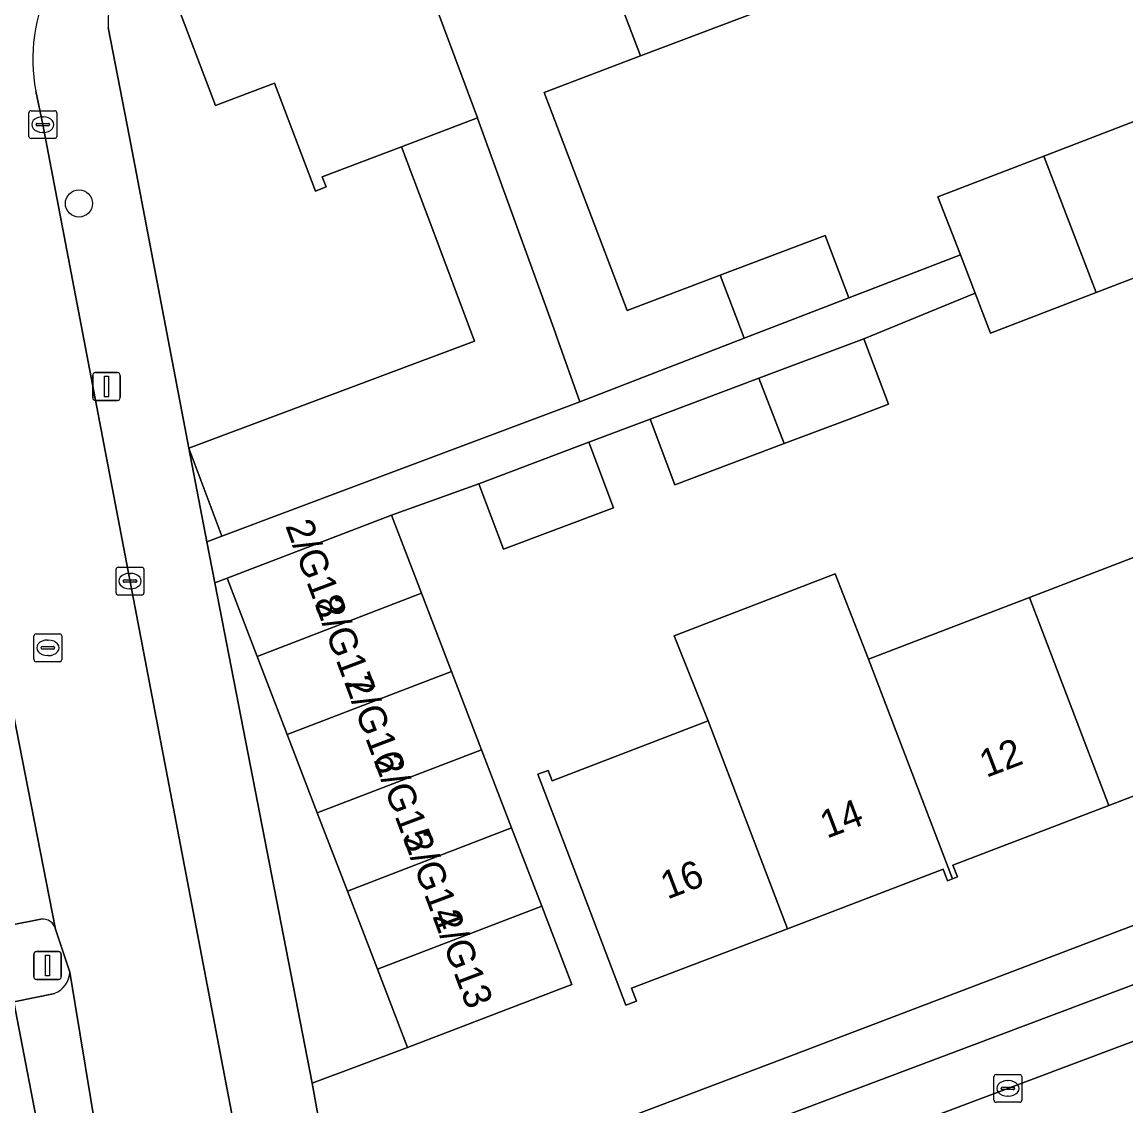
# Model space of a CAD drawing. Extents: x 159262 to 160143, y 383399 to 384319.
# Drawn here: x 159355.19 to 159394.93, y 383839.14 to 383878.17 of the extents above; entities that cross this region are included whole.
import ezdxf

# ---------------------------------------------------------------- set-up
doc = ezdxf.new("R2010")
doc.units = 0
for name, color, linetype in [('IMGEO_Boom', 7, 'Continuous'), ('IMGEO_Erf', 7, 'Continuous'), ('IMGEO_Groenvoorziening', 7, 'Continuous'), ('IMGEO_Kolk', 7, 'Continuous'), ('IMGEO_Lichtmast', 7, 'Continuous'), ('IMGEO_Muur', 7, 'Continuous'), ('IMGEO_Pand', 7, 'Continuous'), ('IMGEO_Pand_nummerreeks', 7, 'Continuous'), ('IMGEO_Parkeervlak_open', 7, 'Continuous'), ('IMGEO_Rijbaan_lokaal_open', 7, 'Continuous'), ('IMGEO_Rioolput', 7, 'Continuous'), ('IMGEO_Voetpad_open', 7, 'Continuous')]:
    doc.layers.add(name, color=color, linetype=linetype)

msp = doc.modelspace()

# ---------------------------------------------------------------- linework, layer by layer
at = {"layer": 'IMGEO_Boom'}
msp.add_circle((159357.24, 383871.637), 0.489, dxfattribs=at)
at = {"layer": 'IMGEO_Erf'}
for points in [[(159364.276, 383875.969), (159362.156, 383875.163), (159360.626, 383879.181), (159362.747, 383879.988), (159362.561, 383880.477), (159362.965, 383880.63), (159363.151, 383880.142), (159368.772, 383882.281), (159374.393, 383884.42), (159374.219, 383884.877), (159374.408, 383884.949), (159374.596, 383885.02), (159374.772, 383884.558), (159380.35, 383886.681), (159385.928, 383888.803), (159385.746, 383889.283), (159385.945, 383889.359), (159386.143, 383889.434), (159386.317, 383888.976), (159391.905, 383891.102), (159397.497, 383893.23)], [(159400.601, 383885.744), (159394.782, 383883.533), (159388.995, 383881.334), (159383.217, 383879.139), (159377.449, 383876.947), (159373.982, 383875.629), (159376.97, 383867.779), (159380.322, 383869.052), (159384.098, 383870.487), (159384.955, 383868.233), (159388.968, 383869.781), (159388.161, 383871.871), (159391.972, 383873.342), (159395.894, 383874.856)], [(159358.297, 383877.978), (159359.054, 383874.019), (159361.194, 383862.82), (159371.476, 383866.674), (159369.937, 383870.778), (159368.849, 383873.679), (159365.998, 383872.596), (159366.138, 383872.23), (159365.755, 383872.084), (159364.276, 383875.969)], [(159397.789, 383869.946), (159393.849, 383868.425), (159390.056, 383866.962), (159389.5, 383868.402), (159385.489, 383866.763), (159386.378, 383864.405), (159384.999, 383863.885), (159382.63, 383862.992), (159378.689, 383861.507), (159377.8, 383863.866), (159375.594, 383863.034), (159376.483, 383860.676), (159372.524, 383859.184), (159371.635, 383861.542), (159368.487, 383860.413), (159369.569, 383857.597), (159370.651, 383854.78), (159371.732, 383851.964), (159372.814, 383849.148), (159373.896, 383846.331), (159374.978, 383843.515), (159369.061, 383841.246), (159365.629, 383839.957), (159366.048, 383837.703)], [(159399.926, 383852.101), (159394.31, 383849.955), (159388.697, 383847.811), (159388.86, 383847.385), (159388.682, 383847.317), (159388.504, 383847.249), (159388.346, 383847.662), (159382.74, 383845.52), (159377.134, 383843.378), (159377.312, 383842.912), (159376.931, 383842.766), (159375.147, 383847.437), (159373.755, 383851.081), (159374.13, 383851.222), (159374.271, 383850.848), (159379.884, 383853.005), (159378.664, 383856.066), (159384.465, 383858.295), (159385.664, 383855.225), (159391.45, 383857.448), (159397.196, 383859.656)], [(159369.194, 383835.764), (159370.416, 383836.226), (159382.457, 383840.783), (159431.75, 383859.554)]]:
    msp.add_lwpolyline(points, dxfattribs=at)
msp.add_arc((159360.856, 383878.173), 2.567, 117.1268, 184.3488, dxfattribs=at)
at = {"layer": 'IMGEO_Groenvoorziening'}
msp.add_lwpolyline([(159356.981, 383832.035), (159354.9, 383842.891)], dxfattribs=at)
at = {"layer": 'IMGEO_Kolk'}
for p, q in [((159355.44, 383874.05), (159355.44, 383874.902)), ((159355.515, 383874.976), (159356.367, 383874.976)), ((159355.928, 383874.756), (159355.953, 383874.756)), ((159356.441, 383874.902), (159356.441, 383874.05)), ((159355.699, 383874.47), (159355.699, 383874.482)), ((159356.137, 383874.433), (159355.739, 383874.433)), ((159355.742, 383874.519), (159356.14, 383874.519)), ((159356.183, 383874.482), (159356.183, 383874.47)), ((159356.367, 383873.976), (159355.515, 383873.976)), ((159355.951, 383874.196), (159355.926, 383874.196)), ((159358.577, 383857.61), (159358.577, 383858.462)), ((159358.652, 383858.536), (159359.504, 383858.536)), ((159359.578, 383858.462), (159359.578, 383857.61)), ((159358.836, 383858.03), (159358.836, 383858.042)), ((159358.879, 383858.079), (159359.277, 383858.079)), ((159359.065, 383858.316), (159359.09, 383858.316)), ((159359.32, 383858.042), (159359.32, 383858.03)), ((159359.274, 383857.993), (159358.876, 383857.993)), ((159359.088, 383857.756), (159359.063, 383857.756)), ((159359.504, 383857.536), (159358.652, 383857.536)), ((159390.177, 383839.342), (159390.177, 383840.194)), ((159390.252, 383840.268), (159391.104, 383840.268)), ((159391.178, 383840.194), (159391.178, 383839.342)), ((159390.436, 383839.762), (159390.436, 383839.774)), ((159390.479, 383839.811), (159390.877, 383839.811)), ((159390.665, 383840.048), (159390.69, 383840.048)), ((159390.92, 383839.774), (159390.92, 383839.762)), ((159390.874, 383839.725), (159390.476, 383839.725)), ((159390.688, 383839.488), (159390.663, 383839.488)), ((159391.104, 383839.268), (159390.252, 383839.268))]:
    msp.add_line(p, q, dxfattribs=at)
for points in [[(159355.44, 383874.05), (159355.44, 383874.902)], [(159355.515, 383874.976), (159356.367, 383874.976)], [(159356.441, 383874.902), (159356.441, 383874.05)], [(159356.367, 383873.976), (159355.515, 383873.976)], [(159358.577, 383857.61), (159358.577, 383858.462)], [(159358.652, 383858.536), (159359.504, 383858.536)], [(159359.578, 383858.462), (159359.578, 383857.61)], [(159359.504, 383857.536), (159358.652, 383857.536)], [(159390.177, 383839.342), (159390.177, 383840.194)], [(159390.252, 383840.268), (159391.104, 383840.268)], [(159391.178, 383840.194), (159391.178, 383839.342)], [(159391.104, 383839.268), (159390.252, 383839.268)]]:
    msp.add_lwpolyline(points, dxfattribs=at)
for centre, radius, start, end in [((159355.517, 383874.9), 0.0765, 91.552, 178.448), ((159355.517, 383874.9), 0.0765, 91.552, 178.448), ((159356.365, 383874.9), 0.0765, 1.552, 88.448), ((159356.365, 383874.9), 0.0765, 1.552, 88.448), ((159355.739, 383874.479), 0.0403, 85.8775, 175.7526), ((159355.736, 383874.469), 0.0366, 178.938, 274.7102), ((159356.14, 383874.476), 0.043, 264.8664, 352.4533), ((159356.144, 383874.481), 0.0386, 1.7309, 96.639), ((159355.517, 383874.052), 0.0765, 181.552, 268.448), ((159355.517, 383874.052), 0.0765, 181.552, 268.448), ((159356.365, 383874.052), 0.0765, 271.552, 358.448), ((159356.365, 383874.052), 0.0765, 271.552, 358.448), ((159358.654, 383858.46), 0.0765, 91.552, 178.448), ((159358.654, 383858.46), 0.0765, 91.552, 178.448), ((159359.502, 383858.46), 0.0765, 1.552, 88.448), ((159359.502, 383858.46), 0.0765, 1.552, 88.448), ((159358.876, 383858.039), 0.0403, 85.8775, 175.7526), ((159359.281, 383858.041), 0.0386, 1.7309, 96.639), ((159358.873, 383858.029), 0.0366, 178.938, 274.7102), ((159359.277, 383858.036), 0.043, 264.8664, 352.4533), ((159358.654, 383857.612), 0.0765, 181.552, 268.448), ((159358.654, 383857.612), 0.0765, 181.552, 268.448), ((159359.502, 383857.612), 0.0765, 271.552, 358.448), ((159359.502, 383857.612), 0.0765, 271.552, 358.448), ((159390.254, 383840.192), 0.0765, 91.552, 178.448), ((159390.254, 383840.192), 0.0765, 91.552, 178.448), ((159391.102, 383840.192), 0.0765, 1.552, 88.448), ((159391.102, 383840.192), 0.0765, 1.552, 88.448), ((159390.476, 383839.771), 0.0403, 85.8775, 175.7526), ((159390.473, 383839.761), 0.0366, 178.938, 274.7102), ((159390.877, 383839.768), 0.043, 264.8664, 352.4533), ((159390.881, 383839.773), 0.0386, 1.7309, 96.639), ((159390.254, 383839.344), 0.0765, 181.552, 268.448), ((159390.254, 383839.344), 0.0765, 181.552, 268.448), ((159391.102, 383839.344), 0.0765, 271.552, 358.448), ((159391.102, 383839.344), 0.0765, 271.552, 358.448)]:
    msp.add_arc(centre, radius, start, end, dxfattribs=at)
for centre, major_axis, ratio, start_param, end_param in [((159355.927, 383874.476), (-0.387, 0.002), 0.722429, 4.712389, 7.853982), ((159355.952, 383874.476), (-0.39, 0.002), 0.717154, 1.570796, 4.712389), ((159359.064, 383858.036), (-0.387, 0.002), 0.722429, 4.712389, 7.853982), ((159359.089, 383858.036), (-0.39, 0.002), 0.717154, 1.570796, 4.712389), ((159390.664, 383839.768), (-0.387, 0.002), 0.722429, 4.712389, 7.853982), ((159390.689, 383839.768), (-0.39, 0.002), 0.717154, 1.570796, 4.712389)]:
    msp.add_ellipse(centre, major_axis=major_axis, ratio=ratio, start_param=start_param, end_param=end_param, dxfattribs=at)
at = {"layer": 'IMGEO_Lichtmast'}
for p, q in [((159357.734, 383864.644), (159357.734, 383865.444)), ((159357.734, 383865.444), (159357.734, 383864.644)), ((159357.834, 383865.544), (159358.624, 383865.544)), ((159358.624, 383865.544), (159357.834, 383865.544)), ((159358.724, 383865.444), (159358.724, 383864.644)), ((159358.724, 383864.644), (159358.724, 383865.444)), ((159358.624, 383864.544), (159357.834, 383864.544)), ((159357.834, 383864.544), (159358.624, 383864.544)), ((159355.613, 383843.793), (159355.613, 383844.593)), ((159355.613, 383844.593), (159355.613, 383843.793)), ((159355.713, 383844.693), (159356.503, 383844.693)), ((159356.503, 383844.693), (159355.713, 383844.693)), ((159356.603, 383844.593), (159356.603, 383843.793)), ((159356.603, 383843.793), (159356.603, 383844.593)), ((159356.503, 383843.693), (159355.713, 383843.693)), ((159355.713, 383843.693), (159356.503, 383843.693))]:
    msp.add_line(p, q, dxfattribs=at)
for points in [[(159358.154, 383865.419), (159358.304, 383865.419), (159358.304, 383864.669), (159358.154, 383864.669), (159358.154, 383865.419)], [(159356.033, 383844.568), (159356.183, 383844.568), (159356.183, 383843.818), (159356.033, 383843.818), (159356.033, 383844.568)]]:
    msp.add_lwpolyline(points, dxfattribs=at)
for centre, start, end in [((159357.834, 383865.444), 90, 180), ((159357.834, 383865.444), 90, 180), ((159358.624, 383865.444), 0, 90), ((159358.624, 383865.444), 360, 90), ((159357.834, 383864.644), 180, 270), ((159357.834, 383864.644), 180, 270), ((159358.624, 383864.644), 270, 0), ((159358.624, 383864.644), 270, 0), ((159355.713, 383844.593), 90, 180), ((159355.713, 383844.593), 90, 180), ((159356.503, 383844.593), 0, 90), ((159356.503, 383844.593), 360, 90), ((159355.713, 383843.793), 180, 270), ((159355.713, 383843.793), 180, 270), ((159356.503, 383843.793), 270, 0), ((159356.503, 383843.793), 270, 0)]:
    msp.add_arc(centre, 0.1, start, end, dxfattribs=at)
at = {"layer": 'IMGEO_Muur'}
msp.add_lwpolyline([(159361.194, 383862.82), (159359.054, 383874.019)], dxfattribs=at)
at = {"layer": 'IMGEO_Pand'}
for points in [[(159380.35, 383886.681), (159374.772, 383884.558), (159374.596, 383885.02), (159374.408, 383884.949), (159377.449, 383876.947), (159383.217, 383879.139)], [(159374.408, 383884.949), (159374.219, 383884.877), (159374.393, 383884.42), (159368.772, 383882.281), (159371.584, 383874.719), (159371.589, 383874.706), (159374.381, 383867.004), (159374.446, 383866.82), (159375.271, 383864.492), (159381.185, 383866.779), (159380.882, 383867.577), (159380.322, 383869.052), (159376.97, 383867.779), (159373.982, 383875.629), (159377.449, 383876.947)], [(159368.772, 383882.281), (159363.151, 383880.142), (159362.965, 383880.63), (159362.561, 383880.477), (159362.747, 383879.988), (159360.626, 383879.181), (159362.156, 383875.163), (159364.276, 383875.969), (159365.755, 383872.084), (159366.138, 383872.23), (159365.998, 383872.596), (159368.849, 383873.679), (159371.584, 383874.719)], [(159396.776, 383872.57), (159395.894, 383874.856), (159391.972, 383873.342), (159393.849, 383868.425), (159397.789, 383869.946), (159397.222, 383871.414)], [(159375.072, 383864.417), (159375.271, 383864.492), (159374.446, 383866.82), (159374.381, 383867.004), (159371.589, 383874.706), (159371.584, 383874.719), (159368.849, 383873.679), (159369.937, 383870.778), (159371.476, 383866.674), (159361.194, 383862.82), (159362.387, 383859.655), (159367.115, 383861.43)], [(159391.972, 383873.342), (159388.161, 383871.871), (159388.968, 383869.781), (159389.5, 383868.402), (159390.056, 383866.962), (159393.849, 383868.425)], [(159380.322, 383869.052), (159380.882, 383867.577), (159381.185, 383866.779), (159384.955, 383868.233), (159384.098, 383870.487)], [(159385.489, 383866.763), (159381.712, 383865.34), (159382.63, 383862.992), (159384.999, 383863.885), (159386.378, 383864.405)], [(159381.712, 383865.34), (159377.8, 383863.866), (159378.689, 383861.507), (159382.63, 383862.992)], [(159372.524, 383859.184), (159376.483, 383860.676), (159375.594, 383863.034), (159371.635, 383861.542)], [(159363.658, 383855.326), (159369.569, 383857.597), (159368.487, 383860.413), (159367.613, 383860.078), (159362.577, 383858.145)], [(159391.45, 383857.448), (159394.31, 383849.955), (159399.926, 383852.101), (159400.088, 383851.677), (159400.222, 383851.728), (159397.196, 383859.656)], [(159388.682, 383847.317), (159385.664, 383855.225), (159384.465, 383858.295), (159378.664, 383856.066), (159379.884, 383853.005), (159382.74, 383845.52), (159388.346, 383847.662), (159388.504, 383847.249)], [(159364.739, 383852.51), (159370.651, 383854.78), (159369.569, 383857.597), (159363.658, 383855.326)], [(159391.45, 383857.448), (159385.664, 383855.225), (159388.682, 383847.317), (159388.86, 383847.385), (159388.697, 383847.811), (159394.31, 383849.955)], [(159364.739, 383852.51), (159365.82, 383849.693), (159371.732, 383851.964), (159370.651, 383854.78)], [(159382.74, 383845.52), (159379.884, 383853.005), (159374.271, 383850.848), (159374.13, 383851.222), (159373.755, 383851.081), (159375.147, 383847.437), (159376.931, 383842.766), (159377.312, 383842.912), (159377.134, 383843.378)], [(159366.901, 383846.876), (159372.814, 383849.148), (159371.732, 383851.964), (159365.82, 383849.693)], [(159366.901, 383846.876), (159367.982, 383844.059), (159373.896, 383846.331), (159372.814, 383849.148)], [(159367.982, 383844.059), (159369.061, 383841.246), (159374.978, 383843.515), (159373.896, 383846.331)]]:
    msp.add_lwpolyline(points, close=True, dxfattribs=at)
at = {"layer": 'IMGEO_Parkeervlak_open'}
for points in [[(159356.402, 383845.497), (159354.446, 383855.504), (159354.311, 383856.268), (159354.188, 383856.861), (159353.566, 383860.305), (159353.392, 383861.174), (159352.333, 383866.611), (159351.349, 383871.798)], [(159350.954, 383871.371), (159346.482, 383870.505), (159348.616, 383859.357), (159349.28, 383855.89), (159351.37, 383844.97), (159355.871, 383845.861)], [(159427.802, 383855.889), (159411.178, 383849.519), (159383.074, 383838.931), (159374.2, 383835.498)], [(159371.844, 383832.486), (159383.623, 383837.11), (159411.861, 383847.734), (159430.92, 383855.178)]]:
    msp.add_lwpolyline(points, dxfattribs=at)
msp.add_arc((159355.935, 383845.386), 0.48, 13.4362, 97.7026, dxfattribs=at)
at = {"layer": 'IMGEO_Rijbaan_lokaal_open'}
for points in [[(159349.939, 383879.282), (159350.139, 383878.285), (159350.877, 383874.361), (159351.177, 383872.768), (159351.327, 383871.914), (159351.349, 383871.798), (159352.333, 383866.611), (159353.392, 383861.174), (159353.566, 383860.305), (159354.188, 383856.861), (159354.311, 383856.268), (159354.446, 383855.504), (159356.402, 383845.497), (159356.907, 383843.958), (159358.398, 383834.932), (159358.725, 383833.228)], [(159355.936, 383874.476), (159355.685, 383875.681)], [(159363.187, 383836.575), (159363.144, 383836.774), (159355.936, 383874.476)]]:
    msp.add_lwpolyline(points, dxfattribs=at)
msp.add_lwpolyline([(159432.041, 383850.161), (159432.689, 383850.402), (159433.465, 383850.712), (159431.695, 383855.47), (159431.498, 383855.404), (159431.28, 383855.319), (159430.92, 383855.178), (159411.861, 383847.734), (159383.623, 383837.11), (159371.844, 383832.486), (159373.65, 383827.758), (159377.676, 383829.295), (159387.324, 383832.951), (159404.16, 383839.368), (159413.728, 383842.98)], close=True, dxfattribs=at)
msp.add_arc((159361.741, 383876.818), 6.162, 116.8603, 190.6332, dxfattribs=at)
at = {"layer": 'IMGEO_Rioolput'}
for p, q in [((159355.622, 383855.208), (159355.622, 383856.06)), ((159355.697, 383856.134), (159356.549, 383856.134)), ((159356.623, 383856.06), (159356.623, 383855.208)), ((159355.924, 383855.677), (159356.322, 383855.677)), ((159356.11, 383855.914), (159356.135, 383855.914)), ((159355.881, 383855.628), (159355.881, 383855.64)), ((159356.319, 383855.591), (159355.921, 383855.591)), ((159356.133, 383855.354), (159356.108, 383855.354)), ((159356.365, 383855.64), (159356.365, 383855.628)), ((159356.549, 383855.134), (159355.697, 383855.134))]:
    msp.add_line(p, q, dxfattribs=at)
for points in [[(159355.622, 383855.208), (159355.622, 383856.06)], [(159355.697, 383856.134), (159356.549, 383856.134)], [(159356.623, 383856.06), (159356.623, 383855.208)], [(159356.549, 383855.134), (159355.697, 383855.134)]]:
    msp.add_lwpolyline(points, dxfattribs=at)
for centre, radius, start, end in [((159355.699, 383856.058), 0.0765, 91.552, 178.448), ((159355.699, 383856.058), 0.0765, 91.552, 178.448), ((159356.547, 383856.058), 0.0765, 1.552, 88.448), ((159356.547, 383856.058), 0.0765, 1.552, 88.448), ((159355.921, 383855.637), 0.0403, 85.8775, 175.7526), ((159356.326, 383855.639), 0.0386, 1.7309, 96.639), ((159355.918, 383855.627), 0.0366, 178.938, 274.7102), ((159356.322, 383855.634), 0.043, 264.8664, 352.4533), ((159355.699, 383855.21), 0.0765, 181.552, 268.448), ((159355.699, 383855.21), 0.0765, 181.552, 268.448), ((159356.547, 383855.21), 0.0765, 271.552, 358.448), ((159356.547, 383855.21), 0.0765, 271.552, 358.448)]:
    msp.add_arc(centre, radius, start, end, dxfattribs=at)
for centre, major_axis, ratio, start_param, end_param in [((159356.109, 383855.634), (-0.387, 0.002), 0.722429, 4.712389, 7.853982), ((159356.134, 383855.634), (-0.39, 0.002), 0.717154, 1.570796, 4.712389)]:
    msp.add_ellipse(centre, major_axis=major_axis, ratio=ratio, start_param=start_param, end_param=end_param, dxfattribs=at)
at = {"layer": 'IMGEO_Voetpad_open'}
for points in [[(159362.134, 383857.975), (159361.847, 383859.452), (159361.194, 383862.82), (159359.054, 383874.019), (159358.297, 383877.978)], [(159355.685, 383875.681), (159355.936, 383874.476), (159363.144, 383836.774), (159363.187, 383836.575)], [(159355.871, 383845.861), (159351.37, 383844.97), (159349.28, 383855.89), (159348.616, 383859.357), (159346.482, 383870.505), (159350.954, 383871.371)], [(159342.623, 383870.295), (159344.735, 383870.683), (159347.636, 383855.565), (159350.307, 383841.994), (159354.9, 383842.891), (159356.372, 383843.192)], [(159431.75, 383859.554), (159382.457, 383840.783), (159370.416, 383836.226), (159371.844, 383832.486)], [(159366.048, 383837.703), (159365.629, 383839.957), (159362.134, 383857.975)], [(159374.2, 383835.498), (159383.074, 383838.931), (159411.178, 383849.519), (159427.802, 383855.889)], [(159356.907, 383843.958), (159356.402, 383845.497)], [(159356.372, 383843.192), (159354.9, 383842.891), (159356.981, 383832.035), (159358.725, 383833.228), (159358.398, 383834.932), (159356.907, 383843.958)]]:
    msp.add_lwpolyline(points, dxfattribs=at)
for points in [[(159377.8, 383863.866), (159381.712, 383865.34), (159385.489, 383866.763), (159389.5, 383868.402), (159388.968, 383869.781), (159384.955, 383868.233), (159381.185, 383866.779), (159375.271, 383864.492), (159375.072, 383864.417), (159367.115, 383861.43), (159362.387, 383859.655), (159361.847, 383859.452), (159362.134, 383857.975), (159362.577, 383858.145), (159367.613, 383860.078), (159368.487, 383860.413), (159371.635, 383861.542), (159375.594, 383863.034)], [(159361.194, 383862.82), (159361.847, 383859.452), (159362.387, 383859.655)], [(159366.901, 383846.876), (159365.82, 383849.693), (159364.739, 383852.51), (159363.658, 383855.326), (159362.577, 383858.145), (159362.134, 383857.975), (159365.629, 383839.957), (159369.061, 383841.246), (159367.982, 383844.059)]]:
    msp.add_lwpolyline(points, close=True, dxfattribs=at)
for centre, radius, start, end in [((159361.741, 383876.818), 6.162, 116.8603, 190.6332), ((159360.856, 383878.173), 2.567, 117.1268, 184.3488), ((159355.935, 383845.386), 0.48, 13.4362, 97.7026), ((159356.063, 383843.978), 0.844, 291.4625, 358.674), ((159356.063, 383843.978), 0.844, 291.4625, 358.674)]:
    msp.add_arc(centre, radius, start, end, dxfattribs=at)

# ---------------------------------------------------------------- texts
at = {"layer": 'IMGEO_Pand_nummerreeks'}
for s, rotation, p in [('2/G18', 290.6335, (159364.659, 383860.034)), ('2/G17', 290.6335, (159365.717, 383857.224)), ('2/G16', 290.6335, (159366.776, 383854.412)), ('12', 20.8896, (159389.899, 383850.947)), ('2/G15', 290.6335, (159367.835, 383851.599)), ('14', 20.8896, (159384.16, 383848.757)), ('2/G14', 290.6335, (159368.894, 383848.787)), ('16', 20.8896, (159378.419, 383846.566)), ('2/G13', 290.6335, (159369.953, 383845.974))]:
    msp.add_text(s, height=1, rotation=rotation, dxfattribs=at).set_placement(p)

doc.saveas('drawing.dxf')
